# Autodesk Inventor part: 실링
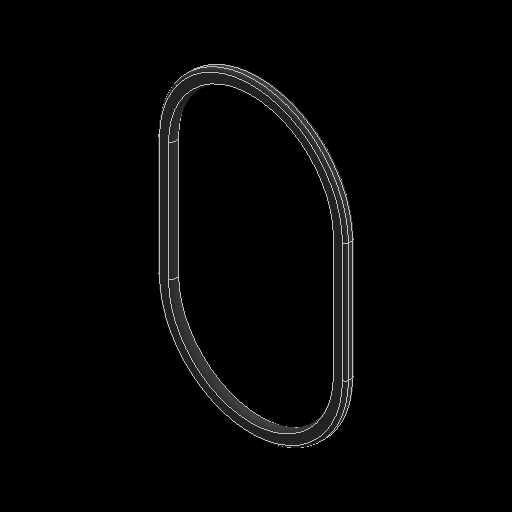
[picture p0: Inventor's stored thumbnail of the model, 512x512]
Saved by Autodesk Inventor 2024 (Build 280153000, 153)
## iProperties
Created: 2025-10
Part Number: 실링
Material: 고무
Document SubType Name: Modeling
Designer: EDU03
Density: 0.93 g/cm^3
Appearance: 기본값
Author: jhkim
Sending System: Autodesk Inventor 2026
Preprocessor: ST-DEVELOPER v20.1
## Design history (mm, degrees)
node "실링1"
node "솔리드1"
node "솔리드3"
